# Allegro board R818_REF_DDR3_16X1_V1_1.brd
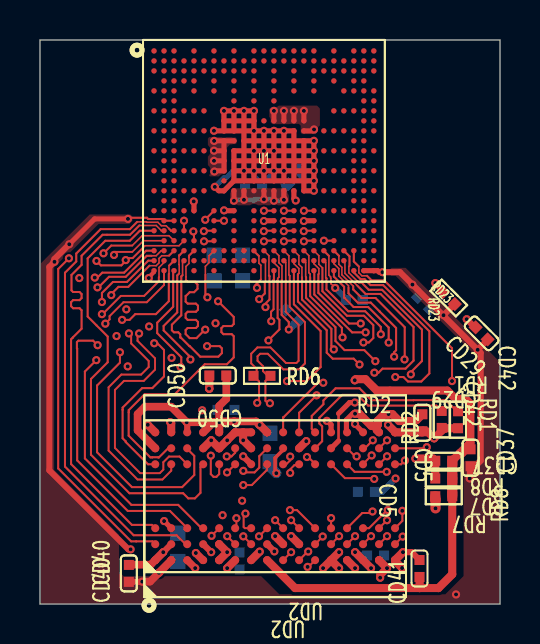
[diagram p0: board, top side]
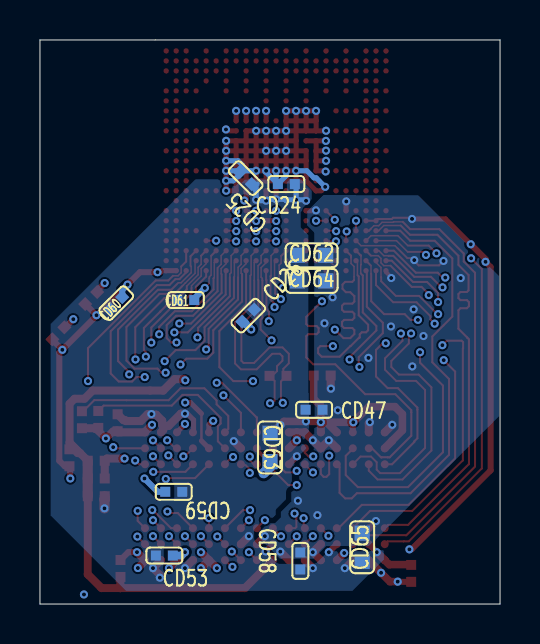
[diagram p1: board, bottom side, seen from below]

Outline 23.03 x 28.24 mm; copper layers: TOP, ART02, ART03, BOTTOM. Coordinates in mm from the lower left corner of the outline.
Outline path: 0,28.24 23.03,28.24 23.03,0 0,0 0,28.24

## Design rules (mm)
net group CLK-ADD-CTR: nets SA0 SA1 SA2 SA3 SA4 SA5 SA6 SA8 SA9 SA10 SA11 SA12 SA13 SA14 SA15 SBA0 SBA1 SBA2 SCKE0 SCKE1 SODT0 SODT1 SRAS SRST SWE
net group DATA0: nets SDQ1 SDQ2 SDQ3 SDQ4 SDQ5 SDQ6 SDQ7
net group DATA1: nets SDQ9 SDQ10 SDQ11 SDQ12 SDQ13 SDQ15 SDQM1

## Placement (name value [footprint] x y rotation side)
CD5  1uF  [C0402]  19.14 9.08 270 top
CD24  1uF  [C0402]  10.7 21.03 0 bottom
CD25  100nF  [C0402]  12.73 21.32 45 bottom
CD26  100nF  [C0402]  12.6 14.44 315 bottom
CD29  100nF  [C0402]  22.1 13.55 315 top
CD37  100nF  [C0402]  20.21 7.17 180 top
CD40  100nF  [C0402]  4.45 1.53 270 top
CD41  100nF  [C0402]  18.99 1.78 90 top
CD42  100nF  [C0402]  21.55 7.32 270 top
CD47  100nF  [C0402]  9.31 9.73 180 bottom
CD50  100nF  [C0402]  8.9 11.44 180 top
CD53  100nF  [C0402]  16.8 2.43 0 bottom
CD58  100nF  [C0402]  9.99 2.16 270 bottom
CD59  100nF  [C0402]  16.33 5.62 180 bottom
CD60  100nF  [C0402]  19.21 15.06 135 bottom
CD61  100nF  [C0402]  15.73 15.22 180 bottom
CD62  10uF  [C0603]  9.43 17.46 180 bottom
CD63  10uF  [C0603]  11.51 7.84 270 bottom
CD64  NC  [C0603]  9.43 16.18 180 bottom
CD65  NC  [C0603]  6.9 2.84 90 bottom
NOREF  -  []  -35.1 -41.09 0 top
RD1  240R-1%  [R0402]  20.11 9.24 270 top
RD2  240R-1%  [R0402]  20.92 9.23 270 top
RD6  100R  [R0402]  11.11 11.42 180 top
RD7  2K-1%  [R0402]  20.21 5.4 0 top
RD8  2K-1%  [R0402]  20.21 6.29 180 top
RD23  240R-1%  [R0402]  20.46 15.32 315 top
U1  R818  [BGA346P50B1200_1200H114]  11.21 22.19 0 top
UD2  DDR3x16  [BGA96P80B1000_1300H120]  11.77 5.4 90 top

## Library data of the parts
CD5 CD24-CD26 CD29 CD37 CD40-CD42 CD47 CD50 CD60-CD65 = C-C0402-X5R_1
CD53 CD58 CD59 = CAPACITOR_0: room: LPDDR3
RD1 RD2 RD7 RD8 RD23 = R-R0402-1%_0
RD6 = R-R0402-5%_1
U1 = R818-BGA-20200107
UD2 = DDR3-FBGA96_0

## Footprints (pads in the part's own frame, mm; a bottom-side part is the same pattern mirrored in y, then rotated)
BGA96P80B1000_1300H120
  round 0.4 smd: A1(-3.2,6) A2(-2.4,6) A3(-1.6,6) A7(1.6,6) A8(2.4,6) A9(3.2,6) B1(-3.2,5.2) B2(-2.4,5.2) B3(-1.6,5.2) B7(1.6,5.2) B8(2.4,5.2) B9(3.2,5.2) C1(-3.2,4.4) C2(-2.4,4.4) C3(-1.6,4.4) C7(1.6,4.4) C8(2.4,4.4) C9(3.2,4.4) D1(-3.2,3.6) D2(-2.4,3.6) D3(-1.6,3.6) D7(1.6,3.6) D8(2.4,3.6) D9(3.2,3.6) E1(-3.2,2.8) E2(-2.4,2.8) E3(-1.6,2.8) E7(1.6,2.8) E8(2.4,2.8) E9(3.2,2.8) F1(-3.2,2) F2(-2.4,2) F3(-1.6,2) F7(1.6,2) F8(2.4,2) F9(3.2,2) G1(-3.2,1.2) G2(-2.4,1.2) G3(-1.6,1.2) G7(1.6,1.2) G8(2.4,1.2) G9(3.2,1.2) H1(-3.2,0.4) H2(-2.4,0.4) H3(-1.6,0.4) H7(1.6,0.4) H8(2.4,0.4) H9(3.2,0.4) J1(-3.2,-0.4) J2(-2.4,-0.4) J3(-1.6,-0.4) J7(1.6,-0.4) J8(2.4,-0.4) J9(3.2,-0.4) K1(-3.2,-1.2) K2(-2.4,-1.2) K3(-1.6,-1.2) K7(1.6,-1.2) K8(2.4,-1.2) K9(3.2,-1.2) L1(-3.2,-2) L2(-2.4,-2) L3(-1.6,-2) L7(1.6,-2) L8(2.4,-2) L9(3.2,-2) M1(-3.2,-2.8) M2(-2.4,-2.8) M3(-1.6,-2.8) M7(1.6,-2.8) M8(2.4,-2.8) M9(3.2,-2.8) N1(-3.2,-3.6) N2(-2.4,-3.6) N3(-1.6,-3.6) N7(1.6,-3.6) N8(2.4,-3.6) N9(3.2,-3.6) P1(-3.2,-4.4) P2(-2.4,-4.4) P3(-1.6,-4.4) P7(1.6,-4.4) P8(2.4,-4.4) P9(3.2,-4.4) R1(-3.2,-5.2) R2(-2.4,-5.2) R3(-1.6,-5.2) R7(1.6,-5.2) R8(2.4,-5.2) R9(3.2,-5.2) T1(-3.2,-6) T2(-2.4,-6) T3(-1.6,-6) T7(1.6,-6) T8(2.4,-6) T9(3.2,-6)
BGA346P50B1200_1200H114
  round 0.27 smd: A1(-5.5,5.5) A2(-5,5.5) A3(-4.5,5.5) A5(-3.5,5.5) A7(-2.5,5.5) A9(-1.5,5.5) A11(-0.5,5.5) A12(0,5.5) A13(0.5,5.5) A14(1,5.5) A15(1.5,5.5) A16(2,5.5) A17(2.5,5.5) A19(3.5,5.5) A21(4.5,5.5) A22(5,5.5) A23(5.5,5.5) AA1(-5.5,-4.5) AA2(-5,-4.5) AA3(-4.5,-4.5) AA4(-4,-4.5) AA5(-3.5,-4.5) AA6(-3,-4.5) AA7(-2.5,-4.5) AA8(-2,-4.5) AA9(-1.5,-4.5) AA10(-1,-4.5) AA11(-0.5,-4.5) AA12(0,-4.5) AA13(0.5,-4.5) AA14(1,-4.5) AA15(1.5,-4.5) AA16(2,-4.5) AA17(2.5,-4.5) AA18(3,-4.5) AA19(3.5,-4.5) AA20(4,-4.5) AA21(4.5,-4.5) AA22(5,-4.5) AA23(5.5,-4.5) AB1(-5.5,-5) AB2(-5,-5) AB3(-4.5,-5) AB4(-4,-5) AB5(-3.5,-5) AB6(-3,-5) AB7(-2.5,-5) AB8(-2,-5) AB9(-1.5,-5) AB10(-1,-5) AB11(-0.5,-5) AB12(0,-5) AB13(0.5,-5) AB14(1,-5) AB15(1.5,-5) AB16(2,-5) AB17(2.5,-5) AB18(3,-5) AB19(3.5,-5) AB20(4,-5) AB22(5,-5) AB23(5.5,-5) AC1(-5.5,-5.5) AC2(-5,-5.5) AC3(-4.5,-5.5) AC5(-3.5,-5.5) AC7(-2.5,-5.5) AC9(-1.5,-5.5) AC11(-0.5,-5.5) AC13(0.5,-5.5) AC15(1.5,-5.5) AC17(2.5,-5.5) AC19(3.5,-5.5) AC21(4.5,-5.5) AC22(5,-5.5) AC23(5.5,-5.5) B1(-5.5,5) B2(-5,5) B3(-4.5,5) B4(-4,5) B5(-3.5,5) B6(-3,5) B7(-2.5,5) B8(-2,5) B9(-1.5,5) B10(-1,5) B11(-0.5,5) B12(0,5) B13(0.5,5) B14(1,5) B15(1.5,5) B16(2,5) B17(2.5,5) B18(3,5) B19(3.5,5) B20(4,5) B21(4.5,5) B22(5,5) B23(5.5,5) C1(-5.5,4.5) C2(-5,4.5) C3(-4.5,4.5) C4(-4,4.5) C5(-3.5,4.5) C6(-3,4.5) C7(-2.5,4.5) C8(-2,4.5) C9(-1.5,4.5) C10(-1,4.5) C11(-0.5,4.5) C13(0.5,4.5) C15(1.5,4.5) C17(2.5,4.5) C18(3,4.5) C19(3.5,4.5) C20(4,4.5) C21(4.5,4.5) C22(5,4.5) C23(5.5,4.5) D2(-5,4) D3(-4.5,4) D4(-4,4) D5(-3.5,4) D7(-2.5,4) D9(-1.5,4) D11(-0.5,4) D13(0.5,4) D15(1.5,4) D17(2.5,4) D19(3.5,4) D21(4.5,4) D22(5,4) E1(-5.5,3.5) E2(-5,3.5) E3(-4.5,3.5) E5(-3.5,3.5) E7(-2.5,3.5) E9(-1.5,3.5) E11(-0.5,3.5) E13(0.5,3.5) E15(1.5,3.5) E17(2.5,3.5) E20(4,3.5) E21(4.5,3.5) E22(5,3.5) E23(5.5,3.5) F2(-5,3) F3(-4.5,3) F9(-1.5,3) F11(-0.5,3) F13(0.5,3) F22(5,3) F23(5.5,3) G1(-5.5,2.5) G2(-5,2.5) G3(-4.5,2.5) G4(-4,2.5) G5(-3.5,2.5) G6(-3,2.5) G19(3.5,2.5) G20(4,2.5) G21(4.5,2.5) G22(5,2.5) G23(5.5,2.5) H2(-5,2) H3(-4.5,2) H8(-2,2) H9(-1.5,2) H10(-1,2) H11(-0.5,2) H12(0,2) H13(0.5,2) H14(1,2) H15(1.5,2) H16(2,2) H22(5,2) H23(5.5,2) J1(-5.5,1.5) J2(-5,1.5) J3(-4.5,1.5) J4(-4,1.5) J5(-3.5,1.5) J6(-3,1.5) J8(-2,1.5) J9(-1.5,1.5) J10(-1,1.5) J15(1.5,1.5) J16(2,1.5) J18(3,1.5) J19(3.5,1.5) J20(4,1.5) J21(4.5,1.5) J22(5,1.5) J23(5.5,1.5) K2(-5,1) K3(-4.5,1) K8(-2,1) K9(-1.5,1) K10(-1,1) K11(-0.5,1) K12(0,1) K13(0.5,1) K14(1,1) K15(1.5,1) K16(2,1) K21(4.5,1) K22(5,1) L1(-5.5,0.5) L2(-5,0.5) L3(-4.5,0.5) L4(-4,0.5) L5(-3.5,0.5) L6(-3,0.5) L8(-2,0.5) L9(-1.5,0.5) L10(-1,0.5) L14(1,0.5) L15(1.5,0.5) L16(2,0.5) L18(3,0.5) L19(3.5,0.5) L20(4,0.5) L21(4.5,0.5) L22(5,0.5) L23(5.5,0.5) M2(-5,0) M3(-4.5,0) M8(-2,0) M9(-1.5,0) M10(-1,0) M11(-0.5,0) M12(0,0) M13(0.5,0) M14(1,0) M15(1.5,0) M16(2,0) M21(4.5,0) M22(5,0) N1(-5.5,-0.5) N2(-5,-0.5) N3(-4.5,-0.5) N4(-4,-0.5) N5(-3.5,-0.5) N6(-3,-0.5) N8(-2,-0.5) N9(-1.5,-0.5) N15(1.5,-0.5) N16(2,-0.5) N18(3,-0.5) N19(3.5,-0.5) N20(4,-0.5) N21(4.5,-0.5) N22(5,-0.5) N23(5.5,-0.5) P2(-5,-1) P3(-4.5,-1) P8(-2,-1) P9(-1.5,-1) P10(-1,-1) P11(-0.5,-1) P12(0,-1) P13(0.5,-1) P14(1,-1) P15(1.5,-1) P16(2,-1) P21(4.5,-1) P22(5,-1) R1(-5.5,-1.5) R2(-5,-1.5) R3(-4.5,-1.5) R4(-4,-1.5) R5(-3.5,-1.5) R6(-3,-1.5) R8(-2,-1.5) R9(-1.5,-1.5) R10(-1,-1.5) R11(-0.5,-1.5) R12(0,-1.5) R13(0.5,-1.5) R14(1,-1.5) R15(1.5,-1.5) R16(2,-1.5) R18(3,-1.5) R19(3.5,-1.5) R20(4,-1.5) R21(4.5,-1.5) R22(5,-1.5) R23(5.5,-1.5) T2(-5,-2) T3(-4.5,-2) T21(4.5,-2) T22(5,-2) U1(-5.5,-2.5) U2(-5,-2.5) U3(-4.5,-2.5) U4(-4,-2.5) U5(-3.5,-2.5) U7(-2.5,-2.5) U9(-1.5,-2.5) U11(-0.5,-2.5) U13(0.5,-2.5) U15(1.5,-2.5) U17(2.5,-2.5) U18(3,-2.5) U19(3.5,-2.5) U20(4,-2.5) U21(4.5,-2.5) U22(5,-2.5) U23(5.5,-2.5) V2(-5,-3) V3(-4.5,-3) V7(-2.5,-3) V9(-1.5,-3) V11(-0.5,-3) V13(0.5,-3) V15(1.5,-3) V17(2.5,-3) V22(5,-3) V23(5.5,-3) W1(-5.5,-3.5) W2(-5,-3.5) W3(-4.5,-3.5) W4(-4,-3.5) W7(-2.5,-3.5) W9(-1.5,-3.5) W11(-0.5,-3.5) W13(0.5,-3.5) W15(1.5,-3.5) W17(2.5,-3.5) W20(4,-3.5) W21(4.5,-3.5) W22(5,-3.5) W23(5.5,-3.5) Y2(-5,-4) Y3(-4.5,-4) Y4(-4,-4) Y5(-3.5,-4) Y7(-2.5,-4) Y9(-1.5,-4) Y11(-0.5,-4) Y13(0.5,-4) Y15(1.5,-4) Y17(2.5,-4) Y19(3.5,-4) Y22(5,-4) Y23(5.5,-4)
C0402
  rect 0.5x0.5 smd: 1(-0.425,0) 2(0.425,0)
C0603
  rect 0.76x0.76 smd: 1(-0.71,0) 2(0.71,0)
R0402
  rect 0.5x0.5 smd: 1(-0.425,0) 2(0.425,0)

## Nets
GND: CD5.2 CD24.2 CD25.2 CD26.2 CD29.2 CD37.2 CD40.2 CD41.2 CD42.2 CD47.2 CD50.2 CD53.1 CD58.1 CD59.1 CD60.2 CD61.2 CD62.2 CD63.2 CD64.2 CD65.2 RD1.2 RD2.2 RD8.2 RD23.2 U1.A1(GND1) U1.A23(GND2) U1.AA7(GND58) U1.AA11(GND59) U1.AA13(GND60) U1.AA18(GND61) U1.AC1(GND62) U1.AC22(GND63) U1.AC23(GND64) U1.C17(GND3) U1.C19(GND4) U1.H8(GND5) U1.H9(GND6) U1.H10(GND7) U1.H11(GND8) U1.J3(GND9) U1.J8(GND10) U1.J9(GND11) U1.J10(GND12) U1.J15(GND13) U1.J21(GND14) U1.K10(GND15) U1.K11(GND16) U1.K12(GND17) U1.K13(GND18) U1.K14(GND19) U1.K15(GND20) U1.K16(GND21) U1.L9(GND22) U1.L10(GND23) U1.L14(GND24) U1.L15(GND25) U1.L16(GND26) U1.M9(GND27) U1.M10(GND28) U1.M11(GND29) U1.M12(GND30) U1.M13(GND31) U1.M14(GND32) U1.M15(GND33) U1.M16(GND34) U1.N9(GND35) U1.N15(GND36) U1.N16(GND37) U1.N22(GND38) U1.P9(GND39) U1.P10(GND40) U1.P11(GND41) U1.P12(GND42) U1.P13(GND43) U1.P14(GND44) U1.P15(GND45) U1.P16(GND46) U1.R8(GND47) U1.R16(GND48) U1.R21(GND49) U1.U5(GND50) U1.U9(GND51) U1.V2(GND52) U1.V3(GND53) U1.V13(GND54) U1.V15(GND55) U1.V17(GND56) U1.Y4(GND57) UD2.A9(VSS#9) UD2.B1(VSSQ#1) UD2.B3(VSS#6) UD2.B9(VSSQ#7) UD2.D1(VSSQ#2) UD2.D8(VSSQ#5) UD2.E1(VSS#1) UD2.E2(VSSQ#4) UD2.E8(VSSQ#6) UD2.F9(VSSQ#8) UD2.G1(VSSQ#3) UD2.G8(VSS#7) UD2.G9(VSSQ#9) UD2.J2(VSS#5) UD2.J8(VSS#8) UD2.M1(VSS#2) UD2.M9(VSS#10) UD2.P1(VSS#3) UD2.P9(VSS#11) UD2.T1(VSS#4) UD2.T9(VSS#12)
VCC-DRAM: CD5.1 CD24.1 CD25.1 CD26.1 CD40.1 CD47.1 CD50.1 CD53.2 CD58.2 CD59.2 CD60.1 CD61.1 CD62.1 CD63.1 CD64.1 CD65.1 RD7.1 U1.R9(VCC_DRAM1) U1.R10(VCC_DRAM2) U1.R11(VCC_DRAM3) U1.R12(VCC_DRAM4) U1.R13(VCC_DRAM5) U1.R14(VCC_DRAM6) UD2.A1(VDDQ#1) UD2.A8(VDDQ#6) UD2.B2(VDD#3) UD2.C1(VDDQ#2) UD2.C9(VDDQ#9) UD2.D2(VDDQ#4) UD2.D9(VDD#7) UD2.E9(VDDQ#8) UD2.F1(VDDQ#3) UD2.G7(VDD#5) UD2.H2(VDDQ#5) UD2.H9(VDDQ#7) UD2.K2(VDD#4) UD2.K8(VDD#6) UD2.N1(VDD#1) UD2.N9(VDD#8) UD2.R1(VDD#2) UD2.R9(VDD#9)
VDD18-DRAM: CD29.1 U1.R15(VDD18_DRAM)
VDD-CPU: U1.K8(VDD_CPU1) U1.K9(VDD_CPU2) U1.L8(VDD_CPU3) U1.M8(VDD_CPU4) U1.N8(VDD_CPU5)
VDD-SYS: U1.H13(VDD_SYS1) U1.H14(VDD_SYS2) U1.H15(VDD_SYS3) U1.H16(VDD_SYS4) U1.J16(VDD_SYS5)
SA0: U1.AB17(SBG0) UD2.N3(A0)
SA1: U1.AB20(SBG1) UD2.P7(A1)
SA2: U1.U15(SA3) UD2.P3(A2)
SA3: U1.AA17(SA0) UD2.N2(A3)
SA4: U1.AB16(SA13) UD2.P8(A4)
SA5: U1.AC17(SA10) UD2.P2(A5)
SA6: U1.AB18(SA8) UD2.R8(A6)
SA7: U1.W17(SA7) UD2.R2(A7)
SA8: U1.AC19(SA11) UD2.T8(A8)
SA9: U1.AA21(SODT0) UD2.R3(A9)
SA10: U1.AC15(SCS0) UD2.L7(A10)
SA11: U1.AB19(SCS1) UD2.R7(A11)
SA12: U1.AA20(SACT) UD2.N7(A12)
SA13: U1.Y17(SA12) UD2.T3(A13)
SA14: U1.AA19(SA9) UD2.T7(A14)
SA15: U1.AC21(SODT1) UD2.M7(A15)
SBA0: U1.W15(SBA0) UD2.M2(BA0)
SBA1: U1.AB15(SA16) UD2.N8(BA1)
SBA2: U1.Y15(SBA1) UD2.M3(BA2)
SCAS: U1.W13(SA5) UD2.K3(CAS#)
SCKE0: U1.AA16(SCKE0) UD2.K9(CKE0)
SCKE1: U1.AA15(SCKE1) UD2.J9(CKE1)
SCKN: RD6.2 U1.AB14(SCKN) UD2.K7(CK#)
SCKP: RD6.1 U1.AA14(SCKP) UD2.J7(CK)
SCS0: U1.AC13(SA14) UD2.L2(CS0#)
SCS1: U1.AB13(SA1) UD2.L1(CS1#)
SDQ0: U1.Y7(SDQ0) UD2.C8(DQU2)
SDQ1: U1.V7(SDQ1) UD2.B8(DQU6)
SDQ2: U1.Y5(SDQ2) UD2.C3(DQU1)
SDQ3: U1.W7(SDQ3) UD2.A7(DQU4)
SDQ4: U1.W1(SDQ4) UD2.D7(DQU0)
SDQ5: U1.W4(SDQ5) UD2.A2(DQU5)
SDQ6: U1.W2(SDQ6) UD2.A3(DQU7)
SDQ7: U1.W3(SDQ7) UD2.C2(DQU3)
SDQ8: U1.AA1(SDQ8) UD2.G2(DQL6)
SDQ9: U1.AB4(SDQ9) UD2.F8(DQL3)
SDQ10: U1.AB1(SDQ10) UD2.H3(DQL4)
SDQ11: U1.AB3(SDQ11) UD2.H7(DQL7)
SDQ12: U1.AC3(SDQ12) UD2.F7(DQL1)
SDQ13: U1.AA4(SDQ13) UD2.H8(DQL5)
SDQ14: U1.AA3(SDQ14) UD2.F2(DQL2)
SDQ15: U1.AA2(SDQ15) UD2.E3(DQL0)
SDQM0: U1.U7(SDQM0) UD2.D3(DMU)
SDQM1: U1.AA5(SDQM1) UD2.E7(DML)
SDQS0N: U1.Y3(SDQS0N) UD2.B7(DQSU#)
SDQS0P: U1.Y2(SDQS0P) UD2.C7(DQSU)
SDQS1N: U1.AC2(SDQS1N) UD2.G3(DQSL#)
SDQS1P: U1.AB2(SDQS1P) UD2.F3(DQSL)
SODT0: U1.AA12(SA2) UD2.K1(ODT0)
SODT1: U1.AB12(SA15) UD2.J1(ODT1)
SRAS: U1.Y13(SA6) UD2.J3(RAS#)
SRST: U1.U17(SRST) UD2.T2(RESET)
SVREF: CD37.1 CD41.1 CD42.1 RD7.2 RD8.1 UD2.H1(VREFDQ) UD2.M8(VREFCA)
SWE: U1.U13(SA4) UD2.L3(WE)
N19640723: RD23.1 U1.Y19(SZQ)
N21027119: RD2.1 UD2.L9(ZQ1)
N21027121: RD1.1 UD2.L8(ZQ0)

Pads without a net: U1 A2 A3 A5 A7 A9 A11 A12 A13 A14 A15 A16 A17 A19 A21 A22 AA6 AA8 AA9 AA10 AA22 AA23 AB5 AB6 AB7 AB8 AB9 AB10 AB11 AB22 AB23 AC5 AC7 AC9 AC11 B1 B2 B3 B4 B5 B6 B7 B8 B9 B10 B11 B12 B13 B14 B15 B16 B17 B18 B19 B20 B21 B22 B23 C1 C2 C3 C4 C5 C6 C7 C8 C9 C10 C11 C13 C15 C18 C20 C21 C22 C23 D2 D3 D4 D5 D7 D9 D11 D13 D15 D17 D19 D21 D22 E1 E2 E3 E5 E7 E9 E11 E13 E15 E17 E20 E21 E22 E23 F2 F3 F9 F11 F13 F22 F23 G1 G2 G3 G4 G5 G6 G19 G20 G21 G22 G23 H2 H3 H12 H22 H23 J1 J2 J4 J5 J6 J18 J19 J20 J22 J23 K2 K3 K21 K22 L1 L2 L3 L4 L5 L6 L18 L19 L20 L21 L22 L23 M2 M3 M21 M22 N1 N2 N3 N4 N5 N6 N18 N19 N20 N21 N23 P2 P3 P8 P21 P22 R1 R2 R3 R4 R5 R6 R18 R19 R20 R22 R23 T2 T3 T21 T22 U1 U2 U3 U4 U11 U18 U19 U20 U21 U22 U23 V9 V11 V22 V23 W9 W11 W20 W21 W22 W23 Y9 Y11 Y22 Y23

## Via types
v1: diameter 0.406, hole 0.203, TOP to BOTTOM, 221 vias

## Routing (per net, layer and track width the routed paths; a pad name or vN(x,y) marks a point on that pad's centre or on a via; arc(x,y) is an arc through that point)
GND: length 150
  TOP w0.076: U1.AA13 11.96,17.44 11.96,17.09 12.11,16.93 12.11,16.23 12.1,16.22 ; 10.94,17.44 10.96,17.42 10.96,17.06 11.06,16.96 11.06,16.24 ; v1(14.77,15.83) 14.56,16.04 14.56,16.31 14.54,16.33 14.54,16.38 14.46,16.47 14.46,17.43 ; 8.28,16.48 8.28,16.91 8.46,17.09 8.46,17.44 U1.AA7 ; U1.Y4 6.96,17.94 5.26,17.94 5.13,17.81
  TOP w0.097: v1(4.29,17.22) 4.34,17.22 4.44,17.32 4.64,17.32 5.13,17.81
  TOP w0.102: v1(8.38,15.36) 8.28,15.46 8.28,16.48 ; U1.AA18 14.21,17.68 14.46,17.43 ; v1(10.86,15.83) 10.86,15.83 10.8,15.89 10.8,15.99 11.06,16.24 ; v1(4.29,17.22) 4.29,17.17 4.07,16.96 3.05,16.96 v1(2.83,17.18) ; v1(4.4,19.28) 4.46,19.34 5.35,19.34 5.42,19.27 6.12,19.27 U1.V2 U1.V3 ; v1(12.45,13.75) 12.45,14.12 12.1,14.47 12.1,16.22 ; 10.94,17.44 10.71,17.67 U1.AA11 ; 20.76,15.02 RD23.2
  TOP w0.178: UD2.J8 12.17,7.72 11.77,7.32 11.77,6.61 v1(11.83,6.55)
  TOP w0.203: U1.AC1 5.71,16.62 5.45,16.36 v1(5.45,16.32)
  TOP w0.254: U1.L10 U1.M10 ; U1.L10 U1.L9 U1.M9 ; U1.L10 U1.K10 ; U1.L10 v1(10.71,22.69) ; U1.M10 U1.M9 ; U1.M10 v1(10.21,21.69) ; U1.M10 U1.M11 ; v1(11.71,21.69) v1(12.21,21.69) ; v1(11.71,21.69) v1(11.21,21.69) ; v1(11.71,21.69) U1.M13 ; v1(11.71,21.69) U1.P13 ; v1(12.21,21.69) U1.P14 ; v1(12.21,21.69) U1.N15 ; v1(12.21,21.69) U1.M14 ; U1.K13 v1(11.71,23.69) ; U1.K13 v1(11.71,22.69) ; U1.K13 U1.K12 ; U1.K13 U1.K14 ; v1(11.71,23.69) v1(12.21,23.69) ; v1(11.71,23.69) v1(11.21,23.69) ; U1.H8 U1.J8 ; U1.H8 v1(9.21,24.69) v1(9.71,24.69) ; U1.H8 U1.H9 ; U1.J8 U1.J9 ; U1.J8 8.71,23.69 v1(8.71,23.69) ; v1(11.21,19.18) 11.22,19.19 U1.V13 ; v1(1.47,18.01) 2.73,19.28 4.4,19.28 v1(4.4,19.28) ; v1(11.21,21.69) U1.M12 ; v1(11.21,21.69) U1.P12 ; v1(11.21,21.69) v1(10.71,21.69) ; v1(11.71,22.69) U1.L14 ; v1(11.71,22.69) v1(11.21,22.69) ; v1(11.71,22.69) U1.M13 ; U1.P14 U1.P15 ; U1.P14 U1.P13 ; U1.K12 v1(11.21,22.69) ; U1.K12 v1(11.21,23.69) ; U1.K12 U1.K11 ; v1(11.21,22.69) v1(10.71,22.69) ; v1(11.21,22.69) U1.M12 ; U1.K15 U1.L15 ; U1.K15 U1.K16 ; U1.K15 U1.J15 v1(12.21,23.69) ; U1.K15 U1.K14 ; U1.L15 U1.L14 ; U1.L15 U1.L16 ; U1.L15 U1.M15 ; v1(13.71,21.69) v1(13.71,22.19) ; v1(13.71,21.69) v1(13.71,21.19) ; v1(13.71,21.69) U1.N16 ; v1(13.71,22.19) v1(13.71,22.69) ; v1(13.71,22.19) U1.M16 ; U1.L14 U1.M14 ; U1.L14 U1.K14 ; U1.H10 U1.H11 ; U1.H10 v1(10.21,24.69) ; U1.H10 U1.J10 ; U1.H10 U1.H9 ; U1.H11 v1(10.71,23.69) ; U1.H11 v1(10.71,24.69) v1(10.21,24.69) ; U1.L16 U1.M16 ; U1.L16 U1.K16 ; U1.L16 v1(13.71,22.69) ; v1(12.21,23.69) U1.K14 ; U1.K16 v1(13.71,23.19) v1(13.71,22.69) ; U1.M16 U1.N16 ; U1.M16 U1.M15 ; v1(11.21,23.69) v1(10.71,23.69) ; U1.P9 U1.P10 ; U1.P9 U1.N9 ; U1.P9 U1.R8 8.95,20.69 v1(8.75,20.89) ; U1.P10 v1(10.21,21.69) ; U1.P10 U1.P11 ; U1.AC22 U1.AC23 16.9,16.69 16.97,16.62 17.13,16.62 17.13,16.61 v1(17.14,16.61) ; v1(10.21,24.69) v1(9.71,24.69) ; U1.K10 U1.K11 ; U1.K10 U1.J10 ; U1.K11 v1(10.71,22.69) ; U1.K11 v1(10.71,23.69) ; v1(10.71,22.69) U1.M11 ; UD2.B3 6.26,4.1 6.26,4.15 v1(6.21,4.15) ; U1.M13 U1.M14 ; U1.M13 U1.M12 ; U1.M14 U1.M15 ; U1.M12 U1.M11 ; U1.M15 U1.N15 ; UD2.P9 15.78,8.99 15.78,9 15.77,9.01 v1(15.77,9.02) ; v1(10.21,21.69) U1.N9 ; v1(10.21,21.69) v1(10.71,21.69) ; U1.U9 9.23,19.69 v1(9.21,19.71) ; v1(10.71,23.69) U1.J10 ; U1.N15 U1.P15 ; U1.N15 U1.N16 ; U1.P15 U1.P16 ; U1.P11 v1(10.71,21.69) ; U1.P11 U1.P12 ; v1(13.71,21.19) v1(13.71,20.69) U1.R16 U1.P16 ; v1(13.71,21.19) U1.P16 ; v1(12.21,19.18) 12.22,19.19 U1.V15 ; U1.N9 U1.M9 ; U1.N16 U1.P16 ; v1(9.71,24.69) U1.H9 ; v1(7.7,20.16) 7.71,20.16 7.71,20.15 U1.U5 ; U1.H9 U1.J9 ; U1.J9 U1.J10 ; v1(10.71,21.69) U1.M11 ; U1.P12 U1.P13 ; v1(14.36,9.17) 14.38,9.17 14.57,8.98 UD2.M9 ; v1(13.21,19.18) 13.22,19.19 U1.V17
  TOP w0.305: CD40.2 5.11,1.11 v1(5.12,1.12) ; v1(4.54,2.74) 4.42,2.74 0.47,6.69 0.47,16.88 v1(0.73,17.13) 0.73,17.27 v1(1.47,18.01) ; v1(18.17,2.6) 18.6,2.6 CD41.2 ; v1(20.2,14.46) 20.76,15.02 ; v1(20.2,14.46) 20.2,14.44 v1(21.91,12.73) ; v1(20.2,14.46) 20.17,14.46 v1(18.64,15.99) 18.02,16.61 v1(17.14,16.61) ; v1(21.91,12.73) 22.4,13.22 CD29.2 ; v1(21.91,12.73) 22.06,12.58 22.06,7.17 21.78,6.9 CD42.2 21.52,6.86 21.52,6.3 v1(21.51,6.29)
  TOP w0.381: v1(5.12,1.12) 5.51,1.12 v1(5.95,1.56) ; v1(7.8,2.56) 8.16,2.2 UD2.D1 ; RD1.2 20.11,8.67 v1(19.73,8.29) 19.37,8.65 CD5.2
  TOP w0.4: UD2.G8 v1(10.17,8.2) 10.17,8.6 ; UD2.T9 17.77,8.62 v1(17.42,8.97) ; UD2.J2 v1(11.77,3.4) ; UD2.B1 6.57,2.18 v1(5.95,1.56) ; 10.17,8.6 UD2.F9 v1(9.37,8.2) UD2.E8 v1(8.57,8.2) UD2.D8 ; 10.17,8.6 UD2.G9 ; v1(14.17,1.8) UD2.M1 14.57,2.2 v1(14.97,2.6) ; UD2.B9 6.57,9.05 v1(6.52,9.11) ; UD2.E2 v1(9.37,2.6) UD2.E1 ; v1(15.77,2.6) UD2.P1 v1(16.57,1.8) ; UD2.T1 17.77,2.16 v1(18.12,1.8) ; UD2.A9 v1(5.39,8.97) ; v1(11,2.62) UD2.G1
  TOP w0.406: UD2.T1 v1(18.17,2.6) ; CD50.2 8.48,10.78 8.47,10.78 v1(8.46,10.78) ; v1(18.79,7.28) 19.67,7.28 CD37.2 RD8.2 ; RD2.2 20.12,8.8 RD1.2 ; v1(14.97,1.8) UD2.M1 ; UD2.T9 19.14,8.6 19.17,8.62 19.17,8.68 CD5.2
  BOTTOM w0.254: v1(10.21,21.69) 9.67,21.69 9.31,21.33 9.2,21.33 v1(8.75,20.89) ; v1(11.71,21.69) 11.71,21.61 11.21,21.11 ; 12.85,21.69 13.02,21.51 ; 12.85,21.69 v1(12.21,21.69) ; 12.85,21.69 12.89,21.74 12.89,21.97 13.11,22.19 v1(13.71,22.19) ; 13.02,21.51 13.2,21.69 v1(13.71,21.69) ; 13.02,21.51 13.35,21.19 v1(13.71,21.19) ; v1(11.21,21.69) 11.21,21.11 ; 11.21,21.11 CD24.2 10.71,21.44 v1(10.71,21.69)
  BOTTOM w0.305: v1(14.77,15.83) 15.3,15.3 CD61.2 ; CD59.1 17.13,5.62 v1(17.79,6.29) ; v1(18.64,15.99) 18.91,15.73 CD60.2
  BOTTOM w0.381: v1(15.77,2.6) 15.94,2.43 CD53.1 ; CD26.2 12.84,14.14 v1(12.45,13.75)
  BOTTOM w0.508: v1(11.83,6.55) 11.51,6.87 CD63.2
  vias: v1(1.97,16.32) v1(3.83,13.42) v1(4.32,14.75) v1(4.39,11.9) v1(5.46,13.9) v1(6.59,12.32) v1(8.12,9.7) v1(8.79,14.06) v1(9.14,4.45) v1(10.12,5.17) v1(20.82,0.48)
VCC-DRAM: length 35.3
  TOP w0.254: U1.R9 v1(9.71,20.19) ; U1.R13 v1(11.71,20.19) ; U1.R14 v1(12.21,20.24) ; U1.R10 v1(10.21,20.24) ; v1(15.77,9.53) 15.65,9.53 15.34,9.22 15.34,8.63 UD2.N9 ; U1.R12 v1(11.21,20.26)
  TOP w0.305: UD2.B2 v1(6.17,2.6) ; v1(11.73,2.63) UD2.H2 ; v1(7.34,9.1) 7.34,9.09 7.37,9.07 UD2.C9 ; UD2.G7 v1(10.17,7.4) ; UD2.D2 v1(8.57,2.6)
  TOP w0.356: UD2.C1 v1(7.77,1.8)
  TOP w0.381: UD2.A1 5.54,1.97 4.46,1.97 CD40.1 ; v1(17.37,1.8) 17.03,1.45 v1(17.03,1.32) ; CD50.1 9.33,10.27 8.97,9.91 v1(8.97,9.11) ; 5.4,8.17 5.4,8.18 4.89,8.69 4.89,9.51 5.26,9.88 6.56,9.88 v1(7.34,9.1) 8.96,9.1 v1(8.97,9.11) ; v1(8.97,9.11) 9.01,9.14 v1(9.72,9.14) 10.81,9.14 10.97,8.99
  TOP w0.4: v1(10.99,8.96) 10.97,8.99 10.97,9 UD2.H9 ; UD2.R1 v1(17.37,1.8) ; UD2.D9 8.68,9.11 v1(8.97,9.11) UD2.E9 ; UD2.F1 v1(9.37,1.8) ; UD2.N1 v1(15.77,1.8) ; UD2.R9 16.85,8.71 16.85,8.92 ; v1(6.17,2.6) UD2.A1 ; UD2.K2 v1(12.57,3.4) ; UD2.K8 v1(13.33,8.15) ; UD2.A8 5.4,8.17
  TOP w0.406: CD5.1 18.84,9.21 18.76,9.21 18.72,9.16 17.98,9.16 17.64,9.5 17.48,9.5 17.47,9.51 v1(17.45,9.51) 17.41,9.48 17.21,9.48 16.91,9.18 16.91,8.98 16.85,8.92 16.58,8.92 15.97,9.53 v1(15.77,9.53)
  TOP w0.508: RD7.1 19.78,5.24 19.8,5.23 v1(19.8,4.79)
  BOTTOM w0.254: v1(10.21,20.24) 10.21,20.96 CD24.1 ; v1(10.21,20.24) 9.76,20.24 v1(9.71,20.19) ; v1(10.21,20.24) 10.66,20.24 10.71,20.19 10.78,20.26 v1(11.21,20.26) 11.64,20.26 v1(11.71,20.19) 12.16,20.19 v1(12.21,20.24) 12.21,20.7 ; 12.16,21.03 12.21,20.97 12.21,20.7 ; 12.21,20.7 12.42,20.91
VDD18-DRAM: length 12.7
  TOP w0.254: U1.R15 12.71,20.29 v1(12.8,20.2)
  TOP w0.305: CD29.1 21.76,13.85 v1(21.36,14.26)
  ART03 w0.381: v1(12.8,20.2) 13.5,20.2 14.01,19.69 16.87,19.69 21.36,15.2 v1(21.36,14.26)
VDD-CPU: length 4
  TOP w0.254: U1.K8 U1.L8 ; U1.K8 8.72,23.19 v1(8.71,23.19) ; U1.K8 U1.K9 ; U1.L8 U1.M8 ; U1.L8 8.71,22.69 v1(8.71,22.7) ; U1.M8 U1.N8 8.76,21.69 v1(8.73,21.65) ; U1.M8 v1(8.71,22.19)
VDD-SYS: length 2.5
  TOP w0.254: U1.H15 v1(12.71,24.69) ; U1.H14 v1(12.21,24.69) ; U1.H13 v1(11.71,24.69) ; v1(13.72,23.76) 13.65,23.69 U1.J16 ; U1.H16 v1(13.21,24.69)
SA0: length 19.4
  TOP w0.076: U1.AB17 13.71,17.04 13.96,16.79 13.96,16.53 13.93,16.51
  TOP w0.102: v1(16.65,4.63) 16.57,4.56 16.13,4.56 UD2.N3 ; v1(16.05,14.04) 16.05,14.04 15.47,14.04 13.93,15.58 13.93,16.51
  ART03 w0.102: v1(16.05,14.04) 17.38,14.04 19.8,11.63 19.8,9.51 20.08,9.22 20.08,7.99 16.72,4.63 v1(16.65,4.63)
SA1: length 14.2
  TOP w0.076: U1.AB20 15.26,17.14 15.26,16.56 15.74,16.08 15.75,16.08 15.84,15.98 15.84,15.98 15.9,15.92
  TOP w0.102: v1(16.6,7.44) 16.17,7.01 UD2.P7 ; 15.9,15.92 16.3,15.52 17.04,15.52 18.7,13.87 18.7,12.19 18.3,11.79 17.15,11.79 16.94,11.58 v1(16.74,11.58)
  ART03 w0.102: v1(16.6,7.44) 16.6,7.74 16.3,8.04 16.3,8.35 16.81,8.85 16.81,11.51 v1(16.74,11.58)
SA2: length 23.2
  TOP w0.102: UD2.P3 16.47,3.8 17.37,4.7 v1(17.41,4.7) ; U1.U15 v1(12.21,19.69)
  ART03 w0.102: v1(17.41,4.7) 17.47,4.77 17.47,4.94 20.39,7.85 20.39,9.67 20.11,9.95 20.11,11.74 17.22,14.64 14.72,14.64 12.87,16.49 12.87,17.76 12.84,17.79 12.84,19.05 v1(12.21,19.69)
SA3: length 17.6
  TOP w0.076: U1.AA17 13.96,17.44 13.96,17.01 14.14,16.83
  TOP w0.102: v1(16.19,13.1) 16.46,13.1 16.68,13.32 16.68,13.96 16.21,14.43 15.37,14.43 14.14,15.66 14.14,16.83 ; v1(15.77,3.4) 15.37,3 UD2.N2
  ART03 w0.102: v1(16.19,13.1) 16.19,12.77 15.3,11.88 15.3,9.77 15.4,9.67 15.4,8.71 15.34,8.66 15.34,3.82 v1(15.77,3.4)
SA4: length 12
  TOP w0.076: U1.AB16 13.3,17.1 13.3,16.38 13.32,16.36
  TOP w0.102: v1(16.66,8.2) 16.66,8.2 16.26,7.8 UD2.P8 ; v1(16.78,12.16) 16.23,12.71 15.25,12.71 14.79,13.17 14.79,13.86 13.32,15.33 13.32,16.36
  ART03 w0.102: v1(16.66,8.2) 17.06,8.6 17.06,9.63 17.12,9.69 17.12,10.61 17.11,10.61 17.11,11.83 v1(16.78,12.16)
SA5: length 16
  TOP w0.102: U1.AC17 13.73,16.67 13.73,15.49 15.62,13.6 v1(16.3,13.6) ; UD2.P2 v1(16.57,3.4)
  ART03 w0.102: v1(16.57,3.4) 16.24,3.73 16.24,7.66 15.99,7.91 15.99,8.38 16.48,8.87 16.48,11.08 16.35,11.22 16.35,12.5 16.55,12.7 16.55,13.35 v1(16.3,13.6)
SA6: length 11.9
  TOP w0.076: 14.34,16.31 14.3,16.34 14.3,17.1 U1.AB18
  TOP w0.102: 14.34,16.31 14.34,16.3 14.34,15.75 15.43,14.66 16.27,14.66 17.06,13.87 v1(17.06,13.51) ; UD2.R8 v1(17.37,8.2)
  ART03 w0.102: v1(17.37,8.2) 17.8,8.63 17.8,10.42 17.42,10.81 17.42,12.15 16.88,12.69 16.88,13.32 v1(17.06,13.51)
SA7: length 22.3
  TOP w0.102: U1.W17 13.22,18.69 13.2,18.67 v1(13.2,18.67) ; UD2.R2 v1(17.37,3.4)
  ART03 w0.102: v1(17.37,3.4) 21.3,7.33 21.3,11.42 16.22,16.5 14.5,16.5 13.57,17.42 13.57,18.3 v1(13.2,18.67)
SA8: length 13.1
  TOP w0.102: v1(19.36,7.85) 19.27,7.85 19.21,7.8 UD2.T8 ; v1(17.45,13.09) 17.45,13.84 16.43,14.87 15.69,14.87 15.22,15.34 15.22,15.88 14.71,16.4 U1.AC19
  ART03 w0.102: v1(19.36,7.85) 19.33,7.89 19.33,9.51 19.33,9.52 19.33,11.66 17.9,13.09 v1(17.45,13.09)
SA9: length 18
  TOP w0.076: 15.96,16.9 15.96,16.59 16.11,16.44 16.37,16.44
  TOP w0.102: U1.AA21 15.71,17.15 15.96,16.9 ; 16.37,16.44 16.6,16.2 17.23,16.2 20.62,12.81 v1(20.62,11.16) ; UD2.R3 v1(17.37,4.2)
  ART03 w0.102: v1(20.62,11.16) 20.69,11.09 20.69,7.73 17.78,4.81 17.78,4.57 17.4,4.2 v1(17.37,4.2)
SA10: length 12.1
  TOP w0.102: U1.AC15 12.71,15.01 14.05,13.67 14.05,11.86 13.34,11.16 v1(12.36,11.16) ; v1(13.36,7.36) 13.42,7.36 13.77,7.02 UD2.L7
  ART03 w0.102: v1(12.36,11.16) 12.36,9.65 12.63,9.37 12.63,8.31 13.36,7.58 v1(13.36,7.36)
SA11: length 12.9
  TOP w0.076: U1.AB19 14.71,17.04 14.96,16.79 14.96,16.42 15.44,15.94 15.44,15.83
  TOP w0.102: UD2.R7 v1(17.37,7.4) ; 15.44,15.83 15.44,15.55 15.9,15.09 16.56,15.09 17.01,14.64 17.82,13.82 17.82,12.71 17.72,12.61 v1(17.72,12.39)
  ART03 w0.102: v1(17.37,7.4) 17.5,7.4 18.41,8.3 18.41,9.89 18.41,10.93 18.17,11.17 18.17,11.51 17.72,11.96 17.72,12.38 v1(17.72,12.39)
SA12: length 16.2
  TOP w0.076: 16.18,16.01 16.1,16.08 15.96,16.08 15.46,16.59 15.46,16.9 15.49,16.93
  TOP w0.102: U1.AA20 15.49,17.41 15.49,16.93 ; v1(17.35,6.62) 15.75,6.62 UD2.N7 ; v1(18.56,11.5) 18.57,11.51 18.57,11.62 19.12,12.16 19.12,13.74 17.12,15.73 16.45,15.73 16.18,16.01
  ART03 w0.102: v1(17.35,6.62) 17.35,6.78 18.72,8.14 18.72,9.77 18.72,9.77 18.72,11.34 v1(18.56,11.5)
SA13: length 20.5
  TOP w0.102: UD2.T3 18.14,4.16 v1(18.14,4.67) ; v1(13.21,18.16) 13.21,18.19 U1.Y17
  ART03 w0.102: v1(13.21,18.16) 13.21,17.23 14.25,16.19 16.09,16.19 21,11.29 21,7.6 18.14,4.74 v1(18.14,4.67)
SA14: length 13.6
  TOP w0.076: 14.96,17.44 14.96,17.43 14.96,17.01 15.11,16.86 15.11,16.48 15.68,15.91
  TOP w0.102: 15.68,15.91 15.68,15.75 16.1,15.32 16.79,15.32 18.25,13.86 18.25,12.26 v1(18.24,12.25) ; UD2.T7 18.07,7 v1(18.26,7.18) ; 14.96,17.44 14.71,17.69 U1.AA19
  ART03 w0.102: v1(18.26,7.18) 18.26,7.26 19.02,8.01 19.02,9.64 19.02,9.64 19.02,11.54 18.31,12.26 18.27,12.26 18.25,12.25 v1(18.24,12.25)
SA15: length 17.5
  TOP w0.102: UD2.M7 15.26,6.3 16.69,6.3 v1(16.73,6.26) ; U1.AC21 15.71,16.6 16.05,16.27 16.25,16.27 16.54,15.97 17.18,15.97 19.49,13.66 19.49,11.54 19.08,11.14 18.41,11.14 18.19,11.36 v1(17.78,11.36)
  ART03 w0.102: v1(16.73,6.26) 16.73,6.72 17,6.98 17,7.53 17.26,7.8 17.47,7.8 18.11,8.43 18.11,10.58 17.78,10.91 v1(17.78,11.36)
SBA0: length 18.7
  TOP w0.102: U1.W15 12.22,18.69 12.2,18.67 v1(12.2,18.67) ; UD2.M2 v1(14.97,3.4)
  ART03 w0.102: v1(14.97,3.4) 14.81,3.56 14.81,3.99 15.04,4.22 15.04,9.58 14.98,9.64 14.98,12 15.83,12.85 15.83,13.63 15.21,14.25 14.68,14.25 12.56,16.36 12.56,18.31 v1(12.2,18.67)
SBA1: length 12.8
  TOP w0.076: U1.AB15 12.71,17.04 12.96,16.79 12.96,16.56 12.91,16.51
  TOP w0.102: UD2.N8 15.77,7.39 v1(15.85,7.39) ; v1(15.99,11.99) 15.7,12.28 14.65,12.28 14.35,12.58 14.35,13.71 12.91,15.15 12.91,16.51
  ART03 w0.102: v1(15.85,7.39) 15.65,7.59 15.65,8.39 16.12,8.87 16.12,9.86 16.13,9.86 16.13,11.85 v1(15.99,11.99)
SBA2: length 17
  TOP w0.102: U1.Y15 12.21,18.19 v1(12.21,18.16) ; UD2.M3 v1(14.57,4.3)
  ART03 w0.102: v1(12.21,18.16) 12.26,18.11 12.26,16.21 14.59,13.87 15.13,13.87 15.52,13.48 15.52,13 14.67,12.15 14.67,9.46 14.73,9.4 14.73,4.47 v1(14.57,4.3)
SCAS: length 17.3
  TOP w0.102: U1.W13 11.22,18.69 11.2,18.67 v1(11.2,18.67) ; UD2.K3 v1(12.57,4.2)
  ART03 w0.102: v1(12.57,4.2) 12.51,4.2 11.92,4.79 11.92,5.26 10.95,6.23 10.95,8.07 10.35,8.67 10.35,9.55 10.14,9.75 10.14,16.11 11.49,17.45 11.49,17.76 11.56,17.84 11.56,18.31 v1(11.2,18.67)
SCKE0: length 11.1
  TOP w0.076: 13.52,16.36 13.52,16.52 13.46,16.59 13.46,17.44 U1.AA16
  TOP w0.102: v1(15.14,13.35) 15.12,13.35 15.11,13.36 15.11,13.83 13.52,15.41 13.52,16.36 ; v1(13.84,10.45) 12.97,9.58 UD2.K9
  ART03 w0.102: v1(15.14,13.35) 14.62,13.35 13.81,12.54 13.81,10.49 v1(13.84,10.45)
SCKE1: length 11.1
  TOP w0.076: U1.AA15 12.96,17.44 12.96,17.01 13.11,16.86 13.11,16.35
  TOP w0.102: v1(14.71,12.75) 14.71,12.76 14.7,12.77 14.7,12.81 14.58,12.92 14.58,13.78 13.11,15.25 13.11,16.35 13.11,16.35 ; UD2.J9 12.17,9.33 12.18,9.34 13.92,11.08 v1(14.18,11.08)
  ART03 w0.102: v1(14.18,11.08) 14.18,12.22 v1(14.71,12.75)
SCKN: length 16.1
  TOP w0.076: 12.3,16.2 12.3,17.1 U1.AB14
  TOP w0.097: v1(12.52,6.56) 12.52,6.74 12.73,6.95 12.92,6.95 UD2.K7 ; 12.3,16.2 12.3,14.62 12.94,13.98 12.94,12.18 12.84,12.07 12.31,12.07 11.53,12.85 10.89,12.85 10.57,12.53 10.57,12.05 10.85,11.77 10.85,11.58 RD6.2 10.97,11.14 10.97,10.17 v1(10.87,10.07)
  ART03 w0.097: v1(10.87,10.07) 10.98,9.97 10.98,9.85 10.98,9.59 11.65,8.92 11.65,7.43 12.01,7.07 12.34,7.07 12.52,6.88 v1(12.52,6.56)
SCKP: length 16.1
  TOP w0.076: U1.AA14 12.21,17.68 12.46,17.43 12.46,16.48 12.5,16.44
  TOP w0.097: v1(11.51,10.05) 11.4,10.05 11.28,10.18 11.28,11.17 RD6.1 11.4,11.42 11.16,11.66 11.16,11.9 10.89,12.18 10.89,12.4 11.02,12.53 11.4,12.53 12.18,11.75 12.97,11.75 13.26,12.04 13.26,14.11 12.5,14.87 12.5,16.44 ; UD2.J7 12.33,7 12.52,7.19 v1(12.52,7.38)
  ART03 w0.097: v1(12.52,7.38) 12.14,7.38 11.96,7.56 11.96,9.05 11.3,9.72 11.3,9.79 11.3,9.99 11.35,10.05 v1(11.51,10.05)
SCS0: length 15.4
  TOP w0.102: v1(11.57,14.16) 11.56,14.17 11.56,14.63 11.69,14.76 11.69,16.22 11.71,16.24 U1.AC13 ; v1(14.15,3.38) 14.15,3.38 UD2.L2
  ART03 w0.102: v1(11.57,14.16) 11.56,14.15 11.56,14.06 13.28,12.35 13.28,10.42 13.64,10.05 13.64,9.28 14.38,8.54 14.38,5.04 13.93,4.6 13.93,3.6 v1(14.15,3.38)
SCS1: length 17.7
  TOP w0.076: 11.9,16.21 11.9,16.3 11.96,16.36 11.96,16.84 11.71,17.09 U1.AB13
  TOP w0.102: v1(11.43,13.2) 11.98,13.75 11.98,14.23 11.89,14.32 11.89,16.2 11.9,16.21 ; UD2.L1 13.47,1.9 13.4,1.9 13.39,1.89 v1(13.39,1.86)
  ART03 w0.102: v1(11.43,13.2) 12.72,11.92 12.72,10.12 13.01,9.82 13.01,9.08 13.77,8.32 13.77,5.37 13.32,4.93 13.32,3.1 13.07,2.84 13.07,2.16 13.36,1.86 v1(13.39,1.86)
SDQ0: length 23.4
  TOP w0.102: UD2.C8 7.37,7.77 7.72,7.42 7.72,6.46 7.11,5.85 4.61,5.85 2.86,7.6 2.86,10.94 4,12.09 v1(4,12.61) ; v1(8.21,18.16) 8.21,18.16 8.68,18.16 U1.Y7
  ART03 w0.102: v1(4,12.61) 4.03,12.64 5.92,12.64 7.53,14.25 7.53,16.61 6.93,17.21 6.68,17.21 6.56,17.34 6.56,17.68 6.71,17.83 7.88,17.83 v1(8.21,18.16)
SDQ1: length 22.2
  TOP w0.102: U1.V7 9.21,19.19 v1(9.21,19.19) ; v1(8.91,15.16) 9.7,14.37 9.7,14.02 9.6,13.92 9.18,13.92 9.08,13.82 9.08,13.61 9.18,13.51 9.6,13.51 9.7,13.41 9.7,12.35 9.35,12 8.25,12 6.75,10.51 5.24,10.51 4.44,9.71 4.44,9.61 4.44,9.6 4.44,8.43 5.52,7.34 5.62,7.34 5.62,7.35 5.92,7.35 5.92,7.34 5.96,7.34 6.41,7.8 UD2.B8
  ART03 w0.102: v1(9.21,19.19) 9.1,19.08 9.1,17.06 9,16.96 8.32,16.96 8.22,16.86 8.22,16.66 8.32,16.56 9,16.56 9.1,16.45 9.1,16.25 9,16.15 8.32,16.15 8.22,16.05 8.22,15.85 8.32,15.74 9,15.74 9.1,15.64 9.1,15.35 v1(8.91,15.16)
SDQ2: length 26
  TOP w0.102: v1(2.89,12.96) 2.87,12.96 2.85,12.97 2.85,12.99 2.66,13.18 1.92,13.18 1.85,13.11 1.85,12.8 1.86,12.79 1.86,7.19 4.39,4.66 6.51,4.66 UD2.C3 ; U1.Y5 7.71,18.62 v1(7.68,18.65)
  ART03 w0.102: v1(2.89,12.96) 3.55,12.96 3.61,13.02 5.11,13.02 6.18,14.09 6.18,15.44 5.74,15.89 5.29,15.89 4.79,16.39 4.79,17.69 5.76,18.65 v1(7.68,18.65)
SDQ3: length 21.5
  TOP w0.102: U1.W7 8.22,18.69 8.2,18.67 v1(8.2,18.67) ; UD2.A7 5.41,7 4.29,8.11 4.29,8.14 4.14,8.3 4.14,9.73 4.14,9.73 4.14,9.83 5.11,10.81 5.62,10.81 6.21,11.39 6.21,12.72 5.87,13.06 v1(5.72,13.06)
  ART03 w0.102: v1(5.72,13.06) 5.79,13.06 6.53,13.8 6.53,14.65 6.65,14.77 7.1,14.77 7.22,14.89 7.22,15.06 7.1,15.18 6.65,15.18 6.53,15.3 6.53,15.47 6.65,15.59 7.1,15.59 7.22,15.7 7.22,15.93 7.11,16.03 6.25,16.03 6.12,16.16 6.12,16.36 6.22,16.45 6.72,16.45 6.78,16.52 6.78,16.81 6.71,16.89 5.54,16.89 5.42,17.02 5.42,17.65 5.98,18.22 7.75,18.22 v1(8.2,18.67)
SDQ4: length 22.5
  TOP w0.102: UD2.D7 8.03,6.86 8.03,5.57 7.75,5.29 7.42,5.29 7.17,5.55 4.48,5.55 2.55,7.47 2.55,11.27 3.39,12.1 3.39,13.39 2.83,13.95 2.39,14.39 2.39,17.3 3.27,18.19 4.49,18.19 5,18.69 U1.W1
SDQ5: length 24.2
  TOP w0.102: v1(1.45,17.31) 0.91,16.77 0.91,6.79 4.56,3.14 4.81,3.14 4.81,3.14 5.63,3.14 UD2.A2 ; U1.W4 v1(7.21,19.19)
  ART03 w0.102: v1(1.45,17.31) 2.3,18.16 4.59,18.16 5.62,19.19 v1(7.21,19.19)
SDQ6: length 22.5
  TOP w0.076: 4.97,18.95 5.82,18.95 6.08,18.69
  TOP w0.102: 6.08,18.69 U1.W2 ; UD2.A3 5.6,3.96 4.6,3.96 1.56,7.01 1.56,13.25 1.64,13.33 1.64,13.34 2.08,13.78 2.08,14.71 1.98,14.81 1.66,14.81 1.56,14.91 1.56,15.11 1.66,15.22 1.98,15.22 2.08,15.32 2.08,15.52 1.98,15.62 1.66,15.62 1.58,15.7 1.58,16.47 2.08,16.98 2.08,17.43 3.13,18.49 3.35,18.49 4.51,18.49 4.97,18.95
SDQ7: length 24.4
  TOP w0.076: 4.87,19.13 5.33,19.13 5.35,19.11 5.9,19.11 6.07,18.94 6.31,18.94 6.46,18.79
  TOP w0.102: 4.87,19.13 4.5,18.77 3.04,18.77 1.82,17.55 1.82,17.15 1.25,16.59 1.25,6.88 4.69,3.44 6.84,3.44 7.29,3 UD2.C2 ; 6.46,18.79 6.56,18.69 U1.W3
SDQ8: length 24.7
  TOP w0.102: v1(2.74,16.34) 2.87,16.34 3.12,16.59 4.21,16.59 5.31,17.69 U1.AA1 ; UD2.G2 v1(10.18,3.39)
  ART03 w0.102: v1(2.74,16.34) 2.58,16.34 0.38,14.15 0.38,9.41 6.75,3.04 9.83,3.04 v1(10.18,3.39)
SDQ9: length 20.9
  TOP w0.076: U1.AB4 7.14,17.12 7.14,16.47
  TOP w0.102: UD2.F8 9.77,7.58 9.58,7.39 v1(9.35,7.39) ; 7.14,16.47 7.07,16.4 7.07,14.46 6.6,13.99 6.6,13.71 6.7,13.6 6.92,13.6 7.02,13.5 7.02,13.35 7.03,13.34 7.05,13.34 7.48,12.91 7.5,12.91 8.02,12.38 8.93,12.38 9.1,12.56 9.1,12.8 8.99,12.91 v1(8.36,12.91)
  ART03 w0.102: v1(9.35,7.39) 9.35,7.46 9.01,7.8 9.01,8.37 8.8,8.59 8.31,8.59 8.21,8.69 8.21,9.1 8.24,9.1 8.55,9.41 8.72,9.41 8.86,9.55 8.86,9.85 8.57,10.14 7.55,10.14 7.39,10.3 7.39,10.71 7.54,10.86 7.97,10.86 8.28,11.17 9.1,11.17 9.19,11.26 9.19,11.49 9.1,11.58 8.65,11.58 8.55,11.68 8.55,11.88 8.63,11.96 8.97,11.96 9.11,12.1 9.11,12.26 8.83,12.53 8.83,12.65 8.84,12.66 9.15,12.97 9.15,13.35 9.03,13.47 8.75,13.47 8.58,13.3 8.58,13.29 8.36,13.08 v1(8.36,12.91) 8.32,12.91 8.31,12.9
SDQ10: length 22.3
  TOP w0.102: v1(3.1,15.12) 3.1,15.57 3.65,16.12 4.35,16.12 5.42,17.19 U1.AB1 ; v1(10.96,3.39) UD2.H3
  ART03 w0.102: v1(10.96,3.39) 10.58,3.77 9.53,3.77 9.23,4.08 7.77,4.08 1.3,10.55 1.3,13.38 3.04,15.12 v1(3.1,15.12)
SDQ11: length 20.6
  TOP w0.076: 6.45,16.53 6.46,16.54 6.46,16.94 6.48,16.96
  TOP w0.102: v1(4.11,14.23) 4.48,14.23 4.77,14.51 5.8,14.51 6.45,15.16 6.45,16.53 ; 6.48,16.96 U1.AB3 ; v1(10.18,5.96) 10.6,5.96 11.37,6.72 UD2.H7
  ART03 w0.102: v1(10.18,5.96) 9.98,6.15 8.31,6.15 6.18,8.28 5.49,8.28 2.28,11.49 2.28,12.86 3.07,13.65 3.44,13.65 4.02,14.23 v1(4.11,14.23)
SDQ12: length 20
  TOP w0.102: v1(9.36,6.59) UD2.F7 ; U1.AC3 6.67,16.65 6.67,14.88 5.87,14.08 5.87,13.56 7.07,12.36 7.07,11.9 v1(7.04,11.87)
  ART03 w0.102: v1(7.04,11.87) 7.01,11.9 6.43,11.9 6.42,11.9 5.26,11.9 4.74,11.39 4.24,11.39 3.89,11.74 3.66,11.74 3.4,11.48 3.4,10.95 3.79,10.56 4.04,10.56 4.38,10.9 4.72,10.9 4.93,10.69 4.93,10.36 4.58,10.01 4.58,9.79 4.81,9.57 5.48,9.57 8.45,6.59 v1(9.36,6.59)
SDQ13: length 20.4
  TOP w0.076: 6.96,17.44 6.96,17 6.97,16.99 6.97,16.55
  TOP w0.102: v1(10.18,6.67) 10.25,6.59 10.74,6.59 10.98,6.83 10.98,7.4 UD2.H8 ; 6.97,16.55 6.87,16.45 6.87,14.6 6.19,13.92 6.19,13.7 7.45,12.43 7.45,12.31 v1(7.53,12.24) ; 6.96,17.44 6.98,17.46 U1.AA4
  ART03 w0.102: v1(10.18,6.67) 9.81,7.04 8.44,7.04 6.87,8.6 6.87,9.25 6.66,9.46 6.01,9.46 5.77,9.71 5.77,10.19 5.67,10.29 5.42,10.29 5.31,10.39 5.31,10.59 5.42,10.7 5.67,10.7 5.77,10.8 5.77,11.09 5.67,11.19 5.38,11.19 5.28,11.29 5.28,11.5 5.38,11.6 6.3,11.6 6.48,11.42 7.18,11.42 7.53,11.76 v1(7.53,12.24)
SDQ14: length 22.6
  TOP w0.076: 6.47,17.45 6.46,17.44 6.1,17.44 5.96,17.3 5.96,17.08 5.82,16.94 5.48,16.94
  TOP w0.102: 6.47,17.45 U1.AA3 ; v1(3.57,15.47) 3.57,15.52 3.93,15.88 4.42,15.88 5.48,16.94 ; UD2.F2 v1(9.37,3.4)
  ART03 w0.102: v1(9.37,3.4) 9,3.77 7.65,3.77 0.99,10.43 0.99,13.63 2.84,15.47 2.93,15.47 2.93,15.47 3.56,15.47 v1(3.57,15.47)
SDQ15: length 22
  TOP w0.076: U1.AA2 6.07,17.69 5.82,17.44 5.59,17.44 5.58,17.43
  TOP w0.102: v1(2.88,15.85) 2.93,15.85 3.46,16.38 4.29,16.38 5.34,17.43 5.58,17.43 ; UD2.E3 v1(8.59,3.42)
  ART03 w0.102: v1(8.59,3.42) 7.57,3.42 0.69,10.3 0.69,13.86 2.61,15.78 2.8,15.78 v1(2.88,15.85)
SDQM0: length 24.6
  TOP w0.102: UD2.D3 8.08,3.8 6.92,4.97 4.57,4.97 2.25,7.29 2.25,11.64 v1(2.82,12.21) ; v1(8.27,19.24) 8.29,19.24 8.3,19.25 8.3,19.28 U1.U7
  ART03 w0.102: v1(2.82,12.21) 4.16,12.21 4.27,12.32 6.06,12.32 7.84,14.1 7.84,17.11 8.59,17.86 8.59,18.95 8.3,19.24 v1(8.27,19.24)
SDQM1: length 19.7
  TOP w0.076: 7.46,17.34 7.46,17.05 7.31,16.9 7.31,16.38 7.31,16.22
  TOP w0.102: U1.AA5 7.46,17.44 7.46,17.34 ; 7.31,16.22 7.39,16.13 7.75,16.13 7.88,15.99 7.88,15.78 7.71,15.61 7.49,15.61 7.31,15.43 7.29,15.43 7.29,15.14 7.39,15.04 7.81,15.04 7.91,14.94 7.91,14.73 7.81,14.63 7.39,14.63 7.29,14.53 7.29,14.33 7.39,14.23 7.81,14.23 7.91,14.12 7.91,13.92 7.81,13.82 7.39,13.82 7.29,13.72 7.29,13.51 7.49,13.31 7.83,13.31 8.26,13.74 v1(8.27,13.74) ; UD2.E7 8.97,6.51 8.83,6.37 8.69,6.37 8.55,6.5 v1(8.55,7.43)
  ART03 w0.102: v1(8.27,13.74) 8.27,13.41 7.98,13.13 7.98,12.72 8.22,12.48 8.22,11.7 8,11.48 7.71,11.48 7.32,11.08 6.33,11.08 6.23,10.98 6.23,10.77 6.33,10.67 6.77,10.67 6.87,10.57 6.87,10.29 7.84,9.32 7.84,8.29 8.55,7.58 v1(8.55,7.43)
SDQS0N: length 20.9
  TOP w0.076: U1.Y3 6.46,18.44 5.11,18.44 4.62,17.95
  TOP w0.097: UD2.B7 6.57,6.68 6.13,6.24 4.88,6.24 3.43,7.68 3.43,10.85 4.07,11.49 5.06,11.49 5.44,11.87 5.44,12.17 4.56,13.05 4.56,13.44 v1(4.45,13.55) ; v1(3.18,17.56) 3.57,17.95 4.62,17.95
  ART03 w0.097: v1(4.45,13.55) 4.45,13.92 4.96,14.42 4.96,15.22 3.2,16.98 3.2,17.54 v1(3.18,17.56)
SDQS0P: length 20.4
  TOP w0.076: 4.62,17.63 5.18,18.19 U1.Y2
  TOP w0.097: v1(4.96,13.55) 4.88,13.47 4.88,13.18 5.76,12.3 5.76,11.73 5.19,11.17 4.2,11.17 3.75,10.72 3.75,7.82 5.01,6.55 6,6.55 6.17,6.73 6.17,7.1 6.46,7.38 6.98,7.38 UD2.C7 ; v1(3.71,17.48) 3.71,17.59 3.75,17.63 3.77,17.63 ; 3.71,17.57 3.77,17.63 ; 3.77,17.63 4.62,17.63
  ART03 w0.097: v1(4.96,13.55) 4.96,13.55 4.83,13.67 4.83,13.85 5.27,14.29 5.27,15.35 3.52,17.1 3.52,17.4 3.6,17.48 v1(3.71,17.48)
SDQS1N: length 20.5
  TOP w0.097: U1.AC2 6.21,15.97 5.35,15.11 4.18,15.11 3.48,14.42 3.48,14.25 v1(3.27,14.04) ; v1(10.28,4.53) 10.25,4.53 10.19,4.47 10.19,3.86 10.25,3.8 UD2.G3
  ART03 w0.097: v1(10.28,4.53) 10.25,4.53 10.24,4.52 10.24,4.52 10.23,4.51 10.15,4.51 9.53,5.13 8.59,5.13 6.2,7.52 5.44,7.52 1.93,11.03 1.93,13.02 2.95,14.04 v1(3.27,14.04)
SDQS1P: length 20.5
  TOP w0.076: U1.AB2 6.21,17.1 5.96,16.85 5.96,16.37 5.95,16.36
  TOP w0.097: v1(9.83,4.3) 9.83,3.86 UD2.F3 ; 5.95,16.36 5.95,16.16 5.21,15.43 4.05,15.43 3.15,14.53 3.11,14.53 v1(3.1,14.51)
  ART03 w0.097: v1(3.1,14.51) 2.94,14.36 2.82,14.36 1.61,13.15 1.61,10.9 5.3,7.2 6.06,7.2 8.46,4.81 9.32,4.81 v1(9.83,4.3)
SODT0: length 17.4
  TOP w0.076: U1.AA12 11.46,17.44 11.46,16.44
  TOP w0.102: 11.46,16.44 11.49,16.42 11.49,15.24 11.26,15.02 11.26,14.88 11.27,14.87 v1(11.28,14.87) ; UD2.K1 13.4,2.63 13.42,2.63 v1(13.42,2.63)
  ART03 w0.102: v1(11.28,14.87) 11.28,14.84 11.21,14.77 11.21,13.93 13,12.14 13,11.99 13,10.3 13.36,9.94 13.36,9.16 14.1,8.43 14.1,5.3 13.66,4.86 13.66,3.48 13.67,3.47 13.67,2.88 13.42,2.63 v1(13.42,2.63)
SODT1: length 16.3
  TOP w0.076: U1.AB12 11.28,17.11 11.28,16.15
  TOP w0.102: 11.28,16.15 11.25,16.11 11.25,15.55 v1(10.97,15.27) ; UD2.J1 v1(12.57,2.6)
  ART03 w0.102: v1(12.57,2.6) 12.57,2.8 12.93,3.15 12.93,7.58 12.35,8.15 12.35,9.26 11.94,9.67 11.94,12.14 10.92,13.16 10.92,15.21 v1(10.97,15.27)
SRAS: length 16.9
  TOP w0.102: U1.Y13 11.21,18.19 v1(11.21,18.16) ; UD2.J3 v1(11.77,4.2)
  ART03 w0.102: v1(11.77,4.2) 11.77,4.46 11.45,4.78 11.45,5.2 10.61,6.04 10.61,7.46 10.32,7.75 10.01,7.75 9.77,7.99 9.77,8.44 10.07,8.74 10.07,9.38 9.84,9.62 9.84,16.3 11.21,17.67 v1(11.21,18.16)
SRST: length 23.2
  TOP w0.102: v1(18.15,3.38) UD2.T2 ; U1.U17 v1(13.21,19.69)
  ART03 w0.102: v1(13.21,19.69) 13.85,19.04 13.85,17.69 14.69,16.85 16.3,16.85 21.61,11.54 21.61,7.21 21.12,6.72 21.12,6.71 18.15,3.75 v1(18.15,3.38)
SVREF: length 30.9
  TOP w0.127: 14.94,8.17 14.94,9.54
  TOP w0.254: UD2.M8 14.94,8.17 ; v1(15.76,10.09) 15.5,10.09 14.94,9.54
  TOP w0.4: 19.94,0.8 12.77,0.8 UD2.H1 ; 17.51,10.69 20.39,10.69 20.8,10.28 21.29,10.28 21.54,10.03 21.54,8.08 ; 21.54,8.08 21.01,7.56 ; 21.54,8.08 21.54,7.76 CD42.1 21.32,7.75 21.13,7.56 21.01,7.56 ; 20.63,1.49 RD7.2 ; 21.01,7.56 CD37.1
  TOP w0.406: 19.94,0.8 20.63,1.49 ; 17.51,10.69 16.86,10.69 16.29,11.26 15.81,11.26 v1(15.75,11.2) ; 19,0.8 19,0.8 19,1.35 CD41.1
  TOP w0.508: RD7.2 RD8.1 CD37.1
  ART03 w0.254: v1(15.75,11.2) 15.77,11.19 15.77,10.1 v1(15.76,10.09)
SWE: length 18.8
  TOP w0.102: UD2.L3 12.86,4.7 v1(12.51,4.7) ; U1.U13 v1(11.21,19.69)
  ART03 w0.102: v1(12.51,4.7) 12.51,5.17 11.27,6.42 11.27,8.17 10.62,8.82 10.62,9.77 10.47,9.91 10.47,16 11.79,17.32 11.79,19.1 v1(11.21,19.69)
N19640723: length 7.8
  TOP w0.102: U1.Y19 v1(14.21,18.19)
  TOP w0.305: v1(19.78,16.07) 20.16,15.69 RD23.1
  ART03 w0.102: v1(19.78,16.07) 19.1,16.75 17.76,16.75 17.25,17.27 14.8,17.27 14.21,17.86 v1(14.21,18.19)
N21027119: length 9.4
  TOP w0.102: UD2.L9 13.6,8.76 13.6,9.42 14.19,10 14.19,10.19 14.79,10.8 15.99,10.8 16.59,10.2 18.69,10.2 18.7,10.21 20.3,10.21 20.86,9.65 RD2.1
N21027121: length 8.7
  TOP w0.102: RD1.1 19.84,9.93 16.43,9.93 15.89,10.47 15.13,10.47 13.98,9.33 13.98,9.04 14.12,8.9 14.12,8.15 UD2.L8

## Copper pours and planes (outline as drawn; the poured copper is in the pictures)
GND on TOP: 0.03,0.03 0.03,17.04 2.49,19.5 4.52,19.5 4.63,19.39 4.63,19.19 4.47,19.03 2.94,19.03 0.79,16.88 0.79,6.64 3.96,3.48 3.96,1.62 4.18,1.4 11.07,1.4 11.98,0.49 20.28,0.49 21.2,1.4 21.2,7.09 21.27,7.17 21.8,7.17 21.91,7.28 21.91,12.32 17.8,16.43 17.59,16.43 17.54,16.47 17.54,16.77 17.6,16.83 18.3,16.83 23,12.13 23,0.03
GND on BOTTOM: outline of 96 points within 0.05,2.28 12.04,20.48
GND on ART02: 0.03,0.03 0.03,28.21 23,28.21 23,0.03
GND on ART03: 0.03,0.03 0.03,17.83 2.12,19.92 9.43,19.92 9.54,19.82 9.54,19.61 9.43,19.5 5.55,19.5 4.53,18.48 2.27,18.48 1.1,17.32 1.1,15.32 0.16,14.37 0.16,8.2 6.92,1.43 13.47,1.43 15.09,3.06 18.34,3.06 18.6,3.32 18.6,3.76 21.97,7.13 21.97,11.83 21.7,12.11 21.7,15.34 17.02,20.02 14.06,20.02 13.46,20.62 13.46,21.26 13.57,21.37 18.22,21.37 23,16.59 23,0.03
VCC-DRAM on TOP: 9.52,20.01 9.52,20.74 9.6,20.81 12.36,20.81 12.45,20.72 12.45,20.14 12.27,19.96 9.58,19.96 9.53,20.01
VCC-DRAM on BOTTOM: 5.82,2.23 5.82,2.69 6.12,2.69 6.24,2.82 6.41,2.66 8.64,2.66 9.23,2.07 9.27,2.03 11.02,2.03 12.31,3.32 12.31,3.71 11.92,4.1 11.54,4.1 10.42,5.22 10.42,6.79 9.94,7.27 9.94,7.53 9.6,7.87 9.6,8.5 9.42,8.68 9.42,10.4 9.6,10.58 9.6,18.48 9.97,18.85 9.97,19.62 9.43,20.16 9.43,20.71 9.98,21.26 15.26,21.26 22.5,14.02 22.5,4.43 18.72,0.66 7.39,0.66
VDD-CPU on TOP: 8.4,21.5 8.4,23.31 8.47,23.37 9.77,23.37 9.84,23.3 9.84,23.08 9.78,23.01 9.51,23.01 9.35,22.85 9.35,21.51 9.25,21.41 8.51,21.41 8.41,21.5
VDD-SYS on TOP: 13.87,24.95 14.01,24.81 14.01,23.66 13.88,23.53 13.11,23.53 13.05,23.59 13.05,23.9 13.05,23.9 13.05,23.95 12.96,24.04 12.51,24.04 12.5,24.03 11.63,24.03 11.48,24.17 11.48,24.92 11.51,24.95
